// Mitsubishi GX Works2 project: 21.8电机点动互锁（无互锁）   PLC: FX3U/FX3UC

PROGRAM MAIN
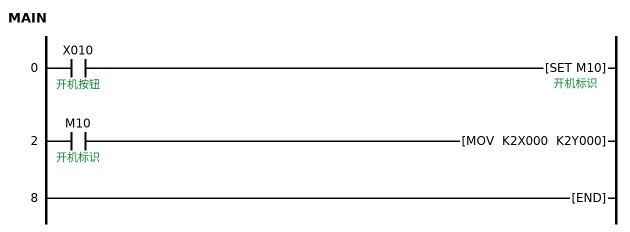
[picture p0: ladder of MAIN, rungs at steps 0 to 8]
0     LD      X010  ; 开机按钮
      SET     M10  ; 开机标识
2     LD      M10  ; 开机标识
      MOV     K2X000 K2Y000  ; 启动按钮 / 电机
8     END
END_PROGRAM

// device comments not shown above
M0  ; 电机运行标识
M20  ; 记录按键情况
